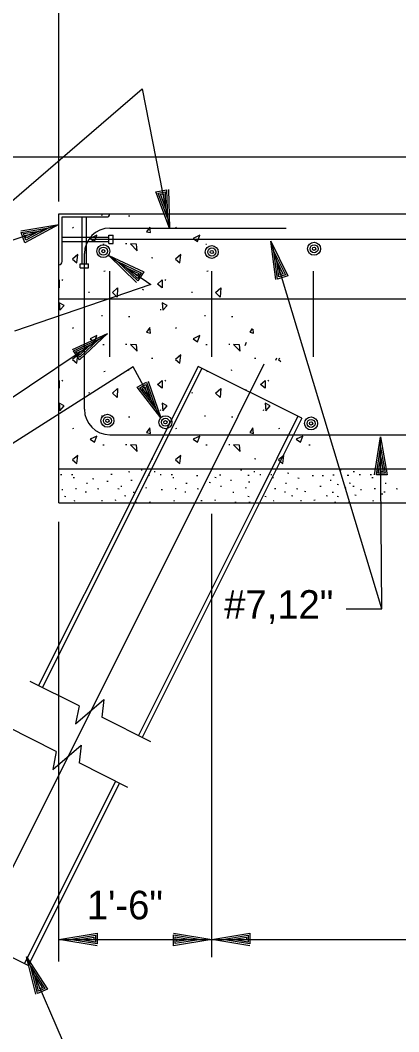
# Model space of a CAD drawing. Extents: x -11983 to -11903, y -13969.5 to -13913.5.
# Drawn here: x -11920.69 to -11916.98, y -13934.76 to -13924.86 of the extents above; entities that cross this region are included whole.
import ezdxf

# ---------------------------------------------------------------- set-up
doc = ezdxf.new("R2010")
doc.units = 0
for name, color, linetype in [('Level 2', 7, 'Continuous'), ('Level 3', 7, 'Continuous'), ('Level 44', 7, 'Continuous'), ('Level 6', 7, 'Continuous')]:
    doc.layers.add(name, color=color, linetype=linetype)

msp = doc.modelspace()

# ---------------------------------------------------------------- linework, layer by layer
at = {"layer": 'Level 2'}
for p, q in [((-11920.3107, -13926.7524), (-11916.3967, -13926.7524)), ((-11920.3107, -13929.5829), (-11920.3107, -13926.7524)), ((-11920.2795, -13926.7836), (-11919.8425, -13926.7836)), ((-11920.2795, -13927.2206), (-11920.2795, -13926.7836)), ((-11920.0817, -13927.2416), (-11920.0817, -13926.7836)), ((-11920.0402, -13927.2416), (-11920.0402, -13926.7836)), ((-11919.8112, -13926.7524), (-11919.8112, -13926.7524)), ((-11920.2795, -13926.9814), (-11919.8217, -13926.9814)), ((-11919.8217, -13927.0439), (-11919.8217, -13926.9606)), ((-11919.8217, -13926.9606), (-11919.78, -13926.9606)), ((-11919.78, -13927.0439), (-11919.78, -13926.9606)), ((-11920.2795, -13927.0229), (-11919.8217, -13927.0229)), ((-11919.8217, -13927.0439), (-11919.78, -13927.0439)), ((-11920.3107, -13927.2519), (-11920.3107, -13927.2519)), ((-11920.1027, -13927.2416), (-11920.0195, -13927.2416)), ((-11920.1027, -13927.2831), (-11920.1027, -13927.2416)), ((-11920.1027, -13927.2831), (-11920.0195, -13927.2831)), ((-11920.0195, -13927.2831), (-11920.0195, -13927.2416)), ((-11919.8112, -13928.1529), (-11919.8112, -13927.3154)), ((-11918.8122, -13928.1529), (-11918.8122, -13927.3154)), ((-11917.8132, -13928.1529), (-11917.8132, -13927.3154)), ((-11920.3107, -13927.5849), (-11912.3187, -13927.5849)), ((-11918.9452, -13928.2466), (-11919.6136, -13929.5829)), ((-11918.9079, -13928.2652), (-11919.5763, -13929.6015)), ((-11917.9298, -13928.7546), (-11918.9452, -13928.2466)), ((-11917.967, -13928.736), (-11918.3813, -13929.5642)), ((-11917.9298, -13928.7546), (-11918.344, -13929.5829)), ((-11919.811, -13928.9169), (-11913.3132, -13928.9169)), ((-11920.3107, -13929.2499), (-11915.944, -13929.2499)), ((-11918.3813, -13929.5642), (-11919.5309, -13931.8634)), ((-11919.6135, -13929.5829), (-11920.5091, -13931.3741)), ((-11919.5762, -13929.6015), (-11920.4718, -13931.3927)), ((-11920.3107, -13929.5829), (-11915.944, -13929.5829)), ((-11918.344, -13929.5829), (-11919.4937, -13931.8821)), ((-11920.1132, -13931.5721), (-11920.593, -13931.3321)), ((-11920.1467, -13931.7499), (-11919.8692, -13931.5106)), ((-11919.8692, -13931.5106), (-11919.8897, -13931.6839)), ((-11920.1132, -13931.5721), (-11920.1467, -13931.7499)), ((-11919.4102, -13931.9239), (-11919.8897, -13931.6839)), ((-11920.3365, -13932.0189), (-11920.8162, -13931.7789)), ((-11920.37, -13932.1966), (-11920.0925, -13931.9574)), ((-11920.3365, -13932.0189), (-11920.37, -13932.1966)), ((-11920.0925, -13931.9574), (-11920.113, -13932.1306)), ((-11919.6335, -13932.3706), (-11920.113, -13932.1306)), ((-11919.7543, -13932.3101), (-11920.6478, -13934.0971)), ((-11919.7171, -13932.3288), (-11920.6106, -13934.1157)), ((-11920.6106, -13934.1157), (-11921.626, -13933.6077))]:
    msp.add_line(p, q, dxfattribs=at)
for centre in [(-11919.8425, -13926.7524), (-11920.3107, -13927.2206)]:
    msp.add_arc(centre, 0.0312, 270, 0, dxfattribs=at)
at = {"layer": 'Level 3'}
for p, q in [((-11920.3107, -13926.6321), (-11920.3107, -13924.3413)), ((-11920.9622, -13926.7916), (-11919.4957, -13925.5301)), ((-11919.4957, -13925.5301), (-11919.2257, -13926.8929)), ((-11922.6515, -13926.1932), (-11916.2094, -13926.1932)), ((-11919.246, -13926.7909), (-11919.246, -13926.7909)), ((-11921.626, -13927.3029), (-11920.3107, -13926.8564)), ((-11920.4092, -13926.8899), (-11920.4092, -13926.8899)), ((-11920.3107, -13926.8564), (-11920.3107, -13926.8564)), ((-11919.2257, -13926.8929), (-11919.2257, -13926.8929)), ((-11917.1452, -13930.6219), (-11918.2337, -13927.0209)), ((-11918.2337, -13927.0209), (-11918.2337, -13927.0209)), ((-11919.8222, -13927.1624), (-11919.4087, -13927.4451)), ((-11919.8222, -13927.1624), (-11919.8222, -13927.1624)), ((-11918.2037, -13927.1204), (-11918.2037, -13927.1204)), ((-11919.7365, -13927.2211), (-11919.7365, -13927.2211)), ((-11919.4087, -13927.4451), (-11920.7467, -13927.9021)), ((-11920.8555, -13928.6094), (-11919.833, -13927.9239)), ((-11919.9195, -13927.9819), (-11919.9195, -13927.9819)), ((-11919.833, -13927.9239), (-11919.833, -13927.9239)), ((-11919.5827, -13928.2504), (-11921.6047, -13929.5339)), ((-11919.3107, -13928.7506), (-11919.5827, -13928.2504)), ((-11918.2998, -13928.2252), (-11918.8122, -13929.2499)), ((-11919.3605, -13928.6594), (-11919.3605, -13928.6594)), ((-11919.3107, -13928.7506), (-11919.3107, -13928.7506)), ((-11917.1452, -13930.6219), (-11917.1567, -13928.9356)), ((-11917.1567, -13928.9356), (-11917.1567, -13928.9356)), ((-11917.156, -13929.0396), (-11917.156, -13929.0396)), ((-11918.8122, -13929.2499), (-11921.5447, -13934.7146)), ((-11920.3107, -13934.0771), (-11920.3107, -13929.7694)), ((-11918.8122, -13934.0336), (-11918.8122, -13929.6907)), ((-11917.494, -13930.6219), (-11917.1452, -13930.6219)), ((-11920.3107, -13933.8594), (-11918.8122, -13933.8594)), ((-11920.3107, -13933.8594), (-11920.3107, -13933.8594)), ((-11920.2067, -13933.8594), (-11920.2067, -13933.8594)), ((-11918.9162, -13933.8594), (-11918.9162, -13933.8594)), ((-11918.8122, -13933.8594), (-11913.8172, -13933.8594)), ((-11918.8122, -13933.8594), (-11918.8122, -13933.8594)), ((-11918.8122, -13933.8594), (-11918.8122, -13933.8594)), ((-11918.7082, -13933.8594), (-11918.7082, -13933.8594)), ((-11919.688, -13936.2051), (-11920.6275, -13934.0294)), ((-11920.6275, -13934.0294), (-11920.6275, -13934.0294)), ((-11920.5862, -13934.1249), (-11920.5862, -13934.1249))]:
    msp.add_line(p, q, dxfattribs=at)
for points in [[(-11919.2375, -13926.5139), (-11919.2257, -13926.8929), (-11919.3592, -13926.5381), (-11919.2552, -13926.5174), (-11919.246, -13926.7909), (-11919.3365, -13926.5499), (-11919.2697, -13926.5366), (-11919.2655, -13926.6929), (-11919.3137, -13926.5616), (-11919.2862, -13926.5561), (-11919.2855, -13926.5906)], [(-11920.6847, -13926.9179), (-11920.3107, -13926.8564), (-11920.645, -13927.0354), (-11920.679, -13926.9349), (-11920.4092, -13926.8899), (-11920.6362, -13927.0111), (-11920.658, -13926.9469), (-11920.504, -13926.9219), (-11920.6275, -13926.9871), (-11920.6365, -13926.9606), (-11920.6025, -13926.9554)], [(-11918.185, -13927.3969), (-11918.2337, -13927.0209), (-11918.0662, -13927.3609), (-11918.1677, -13927.3916), (-11918.2037, -13927.1204), (-11918.09, -13927.3514), (-11918.155, -13927.3711), (-11918.1747, -13927.2161), (-11918.1137, -13927.3419), (-11918.1405, -13927.3499), (-11918.1447, -13927.3156)], [(-11919.5485, -13927.4246), (-11919.8222, -13927.1624), (-11919.4785, -13927.3224), (-11919.5382, -13927.4099), (-11919.7365, -13927.2211), (-11919.503, -13927.3299), (-11919.5415, -13927.3859), (-11919.6537, -13927.2776), (-11919.5275, -13927.3374), (-11919.5432, -13927.3604), (-11919.568, -13927.3361)], [(-11920.1782, -13928.0806), (-11919.833, -13927.9239), (-11920.109, -13928.1836), (-11920.1682, -13928.0956), (-11919.9195, -13927.9819), (-11920.107, -13928.1581), (-11920.1447, -13928.1016), (-11920.0025, -13928.0374), (-11920.1047, -13928.1326), (-11920.1205, -13928.1094), (-11920.0887, -13928.0954)], [(-11919.435, -13928.3924), (-11919.3107, -13928.7506), (-11919.5437, -13928.4516), (-11919.4507, -13928.4011), (-11919.3605, -13928.6594), (-11919.5187, -13928.4561), (-11919.459, -13928.4236), (-11919.4082, -13928.5714), (-11919.4935, -13928.4606), (-11919.4687, -13928.4474), (-11919.458, -13928.4801)], [(-11917.2162, -13929.3101), (-11917.1567, -13928.9356), (-11917.0922, -13929.3091), (-11917.1982, -13929.3099), (-11917.156, -13929.0396), (-11917.1122, -13929.2934), (-11917.1802, -13929.2939), (-11917.1552, -13929.1396), (-11917.1325, -13929.2774), (-11917.1605, -13929.2776), (-11917.1547, -13929.2436)], [(-11919.9367, -13933.9214), (-11920.3107, -13933.8594), (-11919.9367, -13933.7974), (-11919.9367, -13933.9034), (-11920.2067, -13933.8594), (-11919.9527, -13933.8174), (-11919.9527, -13933.8854), (-11920.1067, -13933.8594), (-11919.9687, -13933.8374), (-11919.9687, -13933.8654), (-11920.0027, -13933.8594)], [(-11919.1862, -13933.7974), (-11918.8122, -13933.8594), (-11919.1862, -13933.9214), (-11919.1862, -13933.8154), (-11918.9162, -13933.8594), (-11919.1702, -13933.9014), (-11919.1702, -13933.8334), (-11919.0162, -13933.8594), (-11919.1542, -13933.8814), (-11919.1542, -13933.8534), (-11919.1202, -13933.8594)], [(-11918.4382, -13933.9214), (-11918.8122, -13933.8594), (-11918.4382, -13933.7974), (-11918.4382, -13933.9034), (-11918.7082, -13933.8594), (-11918.4542, -13933.8174), (-11918.4542, -13933.8854), (-11918.6082, -13933.8594), (-11918.4702, -13933.8374), (-11918.4702, -13933.8654), (-11918.5042, -13933.8594)], [(-11920.5362, -13934.3974), (-11920.6275, -13934.0294), (-11920.4222, -13934.3481), (-11920.5197, -13934.3901), (-11920.5862, -13934.1249), (-11920.447, -13934.3414), (-11920.5095, -13934.3684), (-11920.5467, -13934.2166), (-11920.4717, -13934.3346), (-11920.4975, -13934.3456), (-11920.5055, -13934.3121)]]:
    msp.add_lwpolyline(points, dxfattribs=at)
for centre, start, end in [((-11919.811, -13927.1429), 90, 180), ((-11919.811, -13928.6669), 180, 270)]:
    msp.add_arc(centre, 0.25, start, end, dxfattribs=at)
at = {"layer": 'Level 44'}
for p, q in [((-11919.8835, -13926.7686), (-11919.8935, -13926.7669)), ((-11919.6145, -13926.7771), (-11919.628, -13926.7771)), ((-11920.1665, -13926.8864), (-11920.1785, -13926.8924)), ((-11919.1565, -13926.8864), (-11919.1685, -13926.8924)), ((-11919.8675, -13927.0524), (-11919.881, -13927.0524)), ((-11919.6435, -13927.0476), (-11919.6562, -13927.0476)), ((-11918.8637, -13927.0524), (-11918.871, -13927.0524)), ((-11919.389, -13927.1874), (-11919.402, -13927.1851)), ((-11919.8567, -13927.3141), (-11919.8702, -13927.3179)), ((-11919.6237, -13927.3006), (-11919.6335, -13927.3044)), ((-11918.8467, -13927.3141), (-11918.8602, -13927.3179)), ((-11920.2717, -13927.4066), (-11920.283, -13927.3999)), ((-11919.4795, -13927.4996), (-11919.4902, -13927.4946)), ((-11919.2617, -13927.4066), (-11919.273, -13927.3999)), ((-11920.0097, -13927.5236), (-11920.0207, -13927.5246)), ((-11918.9997, -13927.5236), (-11919.0107, -13927.5246)), ((-11919.3067, -13927.6939), (-11919.3167, -13927.6931)), ((-11919.8835, -13927.7524), (-11919.8935, -13927.7506)), ((-11919.6145, -13927.7609), (-11919.628, -13927.7609)), ((-11918.8735, -13927.7524), (-11918.8835, -13927.7506)), ((-11918.6045, -13927.7609), (-11918.618, -13927.7609)), ((-11920.1665, -13927.8701), (-11920.1785, -13927.8761)), ((-11919.1565, -13927.8701), (-11919.1685, -13927.8761)), ((-11919.8675, -13928.0361), (-11919.881, -13928.0361)), ((-11919.6435, -13928.0314), (-11919.6562, -13928.0314)), ((-11918.8575, -13928.0361), (-11918.871, -13928.0361)), ((-11918.6335, -13928.0314), (-11918.6462, -13928.0314)), ((-11919.389, -13928.1711), (-11919.402, -13928.1689)), ((-11918.379, -13928.1711), (-11918.392, -13928.1689)), ((-11919.6237, -13928.2844), (-11919.6335, -13928.2881)), ((-11918.6137, -13928.2844), (-11918.6235, -13928.2881)), ((-11920.2717, -13928.3904), (-11920.283, -13928.3836)), ((-11919.8567, -13928.2979), (-11919.8702, -13928.3016)), ((-11919.2617, -13928.3904), (-11919.273, -13928.3836)), ((-11918.8467, -13928.2979), (-11918.8602, -13928.3016)), ((-11918.2517, -13928.3904), (-11918.263, -13928.3836)), ((-11919.4795, -13928.4834), (-11919.4902, -13928.4784)), ((-11918.4695, -13928.4834), (-11918.4802, -13928.4784)), ((-11920.0097, -13928.5074), (-11920.0207, -13928.5084)), ((-11918.9997, -13928.5074), (-11919.0107, -13928.5084)), ((-11919.3067, -13928.6776), (-11919.3167, -13928.6769)), ((-11918.2967, -13928.6776), (-11918.3067, -13928.6769)), ((-11919.8835, -13928.7361), (-11919.8935, -13928.7344)), ((-11919.6145, -13928.7446), (-11919.628, -13928.7446)), ((-11918.8735, -13928.7361), (-11918.8835, -13928.7344)), ((-11918.6045, -13928.7446), (-11918.618, -13928.7446)), ((-11920.1665, -13928.8539), (-11920.1785, -13928.8599)), ((-11919.1565, -13928.8539), (-11919.1685, -13928.8599)), ((-11918.1465, -13928.8539), (-11918.1585, -13928.8599)), ((-11919.8675, -13929.0199), (-11919.881, -13929.0199)), ((-11919.6435, -13929.0151), (-11919.6562, -13929.0151)), ((-11918.8575, -13929.0199), (-11918.871, -13929.0199)), ((-11918.6335, -13929.0151), (-11918.6462, -13929.0151)), ((-11917.8475, -13929.0199), (-11917.861, -13929.0199)), ((-11919.389, -13929.1549), (-11919.402, -13929.1526)), ((-11918.379, -13929.1549), (-11918.392, -13929.1526)), ((-11919.4943, -13929.2637), (-11919.5053, -13929.2647)), ((-11919.3658, -13929.2787), (-11919.3768, -13929.2795)), ((-11918.518, -13929.2637), (-11918.529, -13929.2647)), ((-11918.3895, -13929.2787), (-11918.4005, -13929.2795)), ((-11917.5418, -13929.2637), (-11917.5528, -13929.2647)), ((-11917.4133, -13929.2787), (-11917.4243, -13929.2795)), ((-11920.2833, -13929.3095), (-11920.2945, -13929.3102)), ((-11920.1743, -13929.3095), (-11920.1868, -13929.3095)), ((-11920.1588, -13929.3387), (-11920.1698, -13929.3395)), ((-11919.9691, -13929.3508), (-11919.9821, -13929.3488)), ((-11919.8266, -13929.3756), (-11919.8396, -13929.3736)), ((-11919.7895, -13929.3074), (-11919.8025, -13929.3054)), ((-11919.6161, -13929.2826), (-11919.6291, -13929.2806)), ((-11919.5933, -13929.3642), (-11919.6043, -13929.3652)), ((-11919.4218, -13929.315), (-11919.4353, -13929.315)), ((-11919.307, -13929.3095), (-11919.3183, -13929.3102)), ((-11919.198, -13929.3095), (-11919.2105, -13929.3095)), ((-11919.1825, -13929.3387), (-11919.1935, -13929.3395)), ((-11918.9473, -13929.3198), (-11918.9603, -13929.3178)), ((-11918.7677, -13929.3384), (-11918.7807, -13929.3364)), ((-11918.7243, -13929.3136), (-11918.7373, -13929.3116)), ((-11918.617, -13929.3642), (-11918.628, -13929.3652)), ((-11918.4455, -13929.315), (-11918.459, -13929.315)), ((-11918.3308, -13929.3095), (-11918.342, -13929.3102)), ((-11918.2218, -13929.3095), (-11918.2343, -13929.3095)), ((-11918.2063, -13929.3387), (-11918.2173, -13929.3395)), ((-11918.0555, -13929.295), (-11918.0685, -13929.293)), ((-11917.9564, -13929.3446), (-11917.9694, -13929.3426)), ((-11917.814, -13929.3198), (-11917.827, -13929.3178)), ((-11917.7149, -13929.3198), (-11917.7279, -13929.3178)), ((-11917.6408, -13929.3642), (-11917.6518, -13929.3652)), ((-11917.6127, -13929.3136), (-11917.6257, -13929.3116)), ((-11917.4693, -13929.315), (-11917.4828, -13929.315)), ((-11917.3545, -13929.3095), (-11917.3658, -13929.3102)), ((-11917.2455, -13929.3095), (-11917.258, -13929.3095)), ((-11917.23, -13929.3387), (-11917.241, -13929.3395)), ((-11920.2723, -13929.456), (-11920.2833, -13929.457)), ((-11920.1368, -13929.445), (-11920.1478, -13929.446)), ((-11920.0303, -13929.3937), (-11920.0413, -13929.3947)), ((-11919.9195, -13929.45), (-11919.9325, -13929.448)), ((-11919.7214, -13929.45), (-11919.7344, -13929.448)), ((-11919.6925, -13929.423), (-11919.7035, -13929.424)), ((-11919.4503, -13929.4377), (-11919.4613, -13929.4385)), ((-11919.296, -13929.456), (-11919.307, -13929.457)), ((-11919.1605, -13929.445), (-11919.1715, -13929.446)), ((-11919.054, -13929.3937), (-11919.065, -13929.3947)), ((-11918.9433, -13929.45), (-11918.9563, -13929.448)), ((-11918.8234, -13929.388), (-11918.8364, -13929.386)), ((-11918.7163, -13929.423), (-11918.7273, -13929.424)), ((-11918.474, -13929.4377), (-11918.485, -13929.4385)), ((-11918.4395, -13929.3818), (-11918.4525, -13929.3798)), ((-11918.3198, -13929.456), (-11918.3308, -13929.457)), ((-11918.1843, -13929.445), (-11918.1953, -13929.446)), ((-11918.0778, -13929.3937), (-11918.0888, -13929.3947)), ((-11917.967, -13929.45), (-11917.98, -13929.448)), ((-11917.8883, -13929.4748), (-11917.9013, -13929.4728)), ((-11917.74, -13929.423), (-11917.751, -13929.424)), ((-11917.5694, -13929.4066), (-11917.5824, -13929.4046)), ((-11917.4978, -13929.4377), (-11917.5088, -13929.4385)), ((-11917.4517, -13929.3942), (-11917.4647, -13929.3922)), ((-11917.4146, -13929.4252), (-11917.4276, -13929.4232)), ((-11917.3435, -13929.456), (-11917.3545, -13929.457)), ((-11917.208, -13929.445), (-11917.219, -13929.446)), ((-11917.1015, -13929.3937), (-11917.1125, -13929.3947)), ((-11916.9908, -13929.45), (-11917.0038, -13929.448)), ((-11920.2416, -13929.5243), (-11920.2546, -13929.5223)), ((-11920.1545, -13929.5635), (-11920.164, -13929.5672)), ((-11920.0413, -13929.4782), (-11920.0523, -13929.479)), ((-11919.8835, -13929.5625), (-11919.8945, -13929.5635)), ((-11919.7513, -13929.559), (-11919.7623, -13929.5597)), ((-11919.6533, -13929.5181), (-11919.6663, -13929.5161)), ((-11919.5715, -13929.4817), (-11919.5825, -13929.4827)), ((-11919.1783, -13929.5635), (-11919.1878, -13929.5672)), ((-11919.065, -13929.4782), (-11919.076, -13929.479)), ((-11918.9073, -13929.5625), (-11918.9183, -13929.5635)), ((-11918.775, -13929.559), (-11918.786, -13929.5597)), ((-11918.5953, -13929.4817), (-11918.6063, -13929.4827)), ((-11918.4457, -13929.5243), (-11918.4587, -13929.5223)), ((-11918.2784, -13929.5243), (-11918.2914, -13929.5223)), ((-11918.202, -13929.5635), (-11918.2115, -13929.5672)), ((-11918.0888, -13929.4782), (-11918.0998, -13929.479)), ((-11918.0184, -13929.5181), (-11918.0314, -13929.5161)), ((-11917.931, -13929.5625), (-11917.942, -13929.5635)), ((-11917.7988, -13929.559), (-11917.8098, -13929.5597)), ((-11917.6778, -13929.5181), (-11917.6908, -13929.5161)), ((-11917.619, -13929.4817), (-11917.63, -13929.4827)), ((-11917.5694, -13929.5243), (-11917.5824, -13929.5223)), ((-11917.396, -13929.5119), (-11917.409, -13929.5099)), ((-11917.2258, -13929.5635), (-11917.2353, -13929.5672)), ((-11917.1359, -13929.4996), (-11917.1489, -13929.4976)), ((-11917.1125, -13929.4782), (-11917.1235, -13929.479)), ((-11919.5495, -13929.5807), (-11919.5605, -13929.5817)), ((-11919.411, -13929.577), (-11919.4245, -13929.5807)), ((-11918.5733, -13929.5807), (-11918.5843, -13929.5817)), ((-11918.4348, -13929.577), (-11918.4483, -13929.5807)), ((-11917.597, -13929.5807), (-11917.608, -13929.5817)), ((-11917.4585, -13929.577), (-11917.472, -13929.5807))]:
    msp.add_line(p, q, dxfattribs=at)
for points in [[(-11919.4125, -13926.9371), (-11919.4195, -13926.8824), (-11919.4502, -13926.9281)], [(-11919.962, -13927.0231), (-11919.9382, -13926.9619), (-11920.0045, -13926.9941)], [(-11919.5497, -13927.0509), (-11919.6097, -13927.0476), (-11919.5447, -13927.1141)], [(-11920.126, -13927.1514), (-11920.1772, -13927.1961), (-11920.1347, -13927.2319)], [(-11919.116, -13927.1514), (-11919.1672, -13927.1961), (-11919.1247, -13927.2319)], [(-11919.7395, -13927.5676), (-11919.7857, -13927.5249), (-11919.7345, -13927.4791)], [(-11919.2972, -13927.4774), (-11919.3452, -13927.4411), (-11919.2992, -13927.4004)], [(-11918.7295, -13927.5676), (-11918.7757, -13927.5249), (-11918.7245, -13927.4791)], [(-11920.3022, -13927.6974), (-11920.2595, -13927.6494), (-11920.3072, -13927.6239)], [(-11919.2922, -13927.6974), (-11919.2495, -13927.6494), (-11919.2972, -13927.6239)], [(-11919.4125, -13927.9209), (-11919.4195, -13927.8661), (-11919.4502, -13927.9119)], [(-11919.962, -13928.0069), (-11919.9382, -13927.9456), (-11920.0045, -13927.9779)], [(-11918.952, -13928.0069), (-11918.9282, -13927.9456), (-11918.9945, -13927.9779)], [(-11919.5497, -13928.0346), (-11919.6097, -13928.0314), (-11919.5447, -13928.0979)], [(-11918.5397, -13928.0346), (-11918.5997, -13928.0314), (-11918.5347, -13928.0979)], [(-11920.126, -13928.1351), (-11920.1772, -13928.1799), (-11920.1347, -13928.2156)], [(-11919.116, -13928.1351), (-11919.1672, -13928.1799), (-11919.1247, -13928.2156)], [(-11919.2972, -13928.4611), (-11919.3452, -13928.4249), (-11919.2992, -13928.3841)], [(-11918.2872, -13928.4611), (-11918.3352, -13928.4249), (-11918.2892, -13928.3841)], [(-11919.7395, -13928.5514), (-11919.7857, -13928.5086), (-11919.7345, -13928.4629)], [(-11918.7295, -13928.5514), (-11918.7757, -13928.5086), (-11918.7245, -13928.4629)], [(-11920.3022, -13928.6811), (-11920.2595, -13928.6331), (-11920.3072, -13928.6076)], [(-11919.2922, -13928.6811), (-11919.2495, -13928.6331), (-11919.2972, -13928.6076)], [(-11918.2822, -13928.6811), (-11918.2395, -13928.6331), (-11918.2872, -13928.6076)], [(-11919.4125, -13928.9046), (-11919.4195, -13928.8499), (-11919.4502, -13928.8956)], [(-11918.4025, -13928.9046), (-11918.4095, -13928.8499), (-11918.4402, -13928.8956)], [(-11919.962, -13928.9906), (-11919.9382, -13928.9294), (-11920.0045, -13928.9616)], [(-11918.952, -13928.9906), (-11918.9282, -13928.9294), (-11918.9945, -13928.9616)], [(-11917.942, -13928.9906), (-11917.9182, -13928.9294), (-11917.9845, -13928.9616)], [(-11919.5497, -13929.0184), (-11919.6097, -13929.0151), (-11919.5447, -13929.0816)], [(-11918.5397, -13929.0184), (-11918.5997, -13929.0151), (-11918.5347, -13929.0816)], [(-11920.126, -13929.1189), (-11920.1772, -13929.1636), (-11920.1347, -13929.1994)], [(-11919.116, -13929.1189), (-11919.1672, -13929.1636), (-11919.1247, -13929.1994)], [(-11918.106, -13929.1189), (-11918.1572, -13929.1636), (-11918.1147, -13929.1994)]]:
    msp.add_lwpolyline(points, close=True, dxfattribs=at)
for points in [[(-11918.9283, -13926.9619), (-11918.9945, -13926.9941), (-11918.952, -13927.0231)], [(-11918.952, -13927.0231), (-11918.9283, -13926.962)], [(-11920.3107, -13927.4017), (-11920.3092, -13927.4004), (-11920.3072, -13927.4774)], [(-11920.3072, -13927.4774), (-11920.3107, -13927.4747)], [(-11918.4155, -13927.8751), (-11918.4402, -13927.9119), (-11918.4025, -13927.9209)], [(-11918.4025, -13927.9209), (-11918.4072, -13927.8839)], [(-11918.1438, -13928.1681), (-11918.1572, -13928.1799), (-11918.1343, -13928.1992)], [(-11920.3107, -13928.3855), (-11920.3092, -13928.3841), (-11920.3072, -13928.4611)], [(-11920.3072, -13928.4611), (-11920.3107, -13928.4585)]]:
    msp.add_lwpolyline(points, dxfattribs=at)
at = {"layer": 'Level 6'}
for p, q in [((-11919.811, -13926.8929), (-11918.083, -13926.8929)), ((-11919.9924, -13927.0021), (-11912.5859, -13927.0021)), ((-11920.061, -13928.6669), (-11920.061, -13927.1429)), ((-11918.4732, -13928.0139), (-11918.4892, -13928.0459)), ((-11918.1782, -13928.1679), (-11918.1885, -13928.1881))]:
    msp.add_line(p, q, dxfattribs=at)
for centre, radius in [((-11919.8752, -13927.1186), 0.0633), ((-11919.8752, -13927.1186), 0.0396), ((-11918.8119, -13927.1268), 0.0633), ((-11918.8119, -13927.1268), 0.0396), ((-11917.8087, -13927.095), 0.0633), ((-11917.8087, -13927.095), 0.0396), ((-11917.8087, -13927.095), 0.0158), ((-11919.8752, -13927.1186), 0.0158), ((-11918.8119, -13927.1268), 0.0158), ((-11919.8352, -13928.7794), 0.0633), ((-11919.8352, -13928.7794), 0.0396), ((-11919.8352, -13928.7794), 0.0158), ((-11919.266, -13928.7941), 0.0633), ((-11919.266, -13928.7941), 0.0396), ((-11919.266, -13928.7941), 0.0158), ((-11917.8383, -13928.8059), 0.0633), ((-11917.8383, -13928.8059), 0.0396), ((-11917.8383, -13928.8059), 0.0158)]:
    msp.add_circle(centre, radius, dxfattribs=at)

# ---------------------------------------------------------------- texts
at = {"layer": 'Level 3'}
for s, p in [('#7,12"', (-11918.6897, -13930.7191)), ('1\'-6"', (-11920.0364, -13933.6633))]:
    msp.add_text(s, height=0.28, dxfattribs=at).set_placement(p)

doc.saveas('drawing.dxf')
